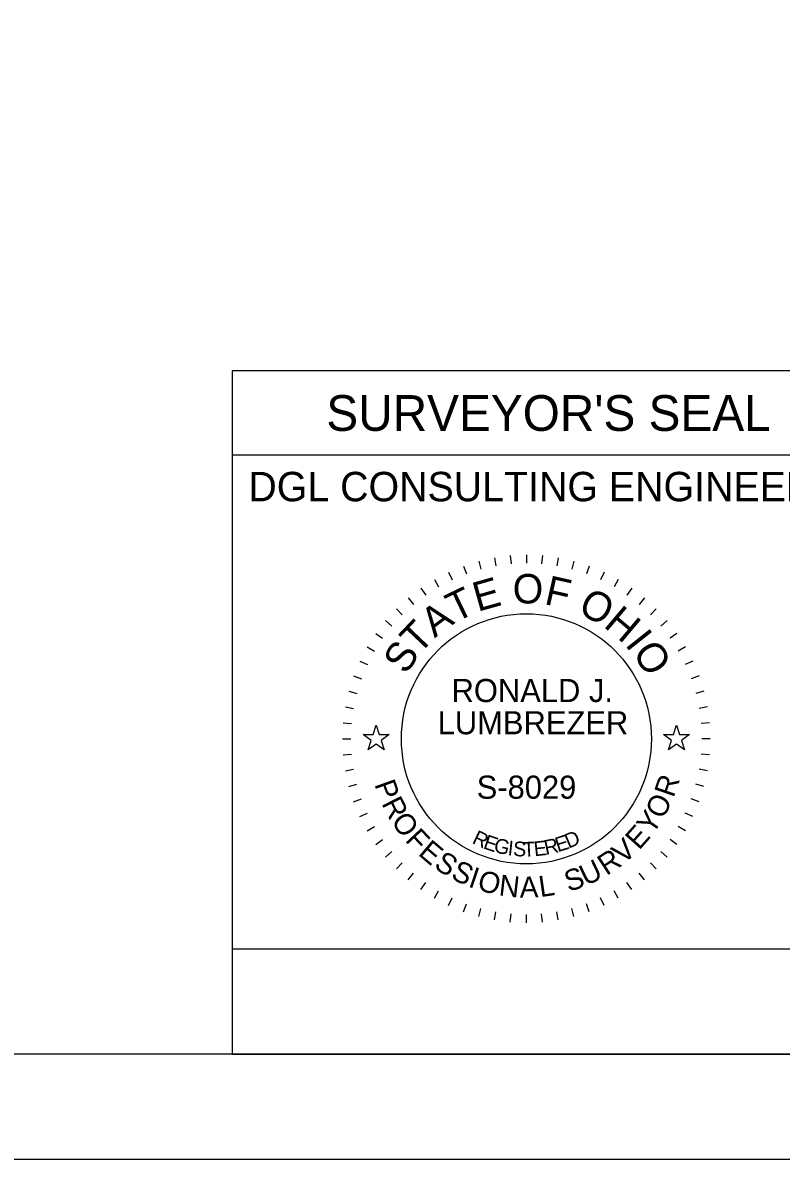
# Model space of a CAD drawing. Extents: x 0 to 34, y 0 to 22.
# Drawn here: x 28.2 to 31.81, y 0 to 5.41 of the extents above; entities that cross this region are included whole.
import ezdxf

# ---------------------------------------------------------------- set-up
doc = ezdxf.new("R2010")
doc.units = 0
for name, color, linetype in [('Default', 7, 'Continuous'), ('SH_Border', 7, 'Continuous'), ('SH_Cut_Line', 7, 'Continuous'), ('SH_Data', 7, 'Continuous')]:
    doc.layers.add(name, color=color, linetype=linetype)

msp = doc.modelspace()

# ---------------------------------------------------------------- linework, layer by layer
at = {"layer": 'Default'}
for points in [[(29.8236, 2.02), (29.8705, 2.02), (29.885, 2.0645), (29.8995, 2.02), (29.9464, 2.02), (29.9085, 1.9924), (29.923, 1.9478), (29.885, 1.9754), (29.847, 1.9478), (29.8615, 1.9924)], [(31.2536, 2.02), (31.3005, 2.02), (31.315, 2.0645), (31.3295, 2.02), (31.3764, 2.02), (31.3385, 1.9924), (31.353, 1.9478), (31.315, 1.9754), (31.277, 1.9478), (31.2915, 1.9924)]]:
    msp.add_lwpolyline(points, close=True, dxfattribs=at)
at = {"layer": 'SH_Border'}
msp.add_lwpolyline([(1.5, 21.5), (33.5, 21.5), (33.5, 0.5), (1.5, 0.5)], close=True, dxfattribs=at)
at = {"layer": 'SH_Cut_Line'}
msp.add_lwpolyline([(0, 0), (34, 0), (34, 22), (0, 22)], close=True, dxfattribs=at)
at = {"layer": 'SH_Data'}
for p, q in [((32, 3.75), (29.2, 3.75)), ((29.2, 3.75), (29.2, 0.5)), ((32, 3.35), (29.2, 3.35)), ((30.5237, 2.8717), (30.5272, 2.8318)), ((30.6, 2.875), (30.6, 2.835)), ((30.6763, 2.8717), (30.6728, 2.8318)), ((30.3007, 2.8222), (30.3144, 2.7846)), ((30.3735, 2.8452), (30.3839, 2.8065)), ((30.4481, 2.8617), (30.455, 2.8223)), ((30.7519, 2.8617), (30.745, 2.8223)), ((30.8265, 2.8452), (30.8161, 2.8065)), ((30.8993, 2.8222), (30.8856, 2.7846)), ((30.1625, 2.7578), (30.1825, 2.7231)), ((30.2302, 2.793), (30.2471, 2.7568)), ((30.9698, 2.793), (30.9529, 2.7568)), ((31.0375, 2.7578), (31.0175, 2.7231)), ((30.0981, 2.7168), (30.1211, 2.684)), ((31.1019, 2.7168), (31.0789, 2.684)), ((30.0376, 2.6703), (30.0633, 2.6396)), ((31.1624, 2.6703), (31.1367, 2.6396)), ((29.9813, 2.6187), (30.0096, 2.5904)), ((31.2187, 2.6187), (31.1904, 2.5904)), ((29.9297, 2.5624), (29.9604, 2.5367)), ((31.2703, 2.5624), (31.2396, 2.5367)), ((29.8832, 2.5019), (29.916, 2.4789)), ((31.3168, 2.5019), (31.284, 2.4789)), ((29.8422, 2.4375), (29.8769, 2.4175)), ((31.3578, 2.4375), (31.3231, 2.4175)), ((29.807, 2.3698), (29.8432, 2.3529)), ((31.393, 2.3698), (31.3568, 2.3529)), ((29.7778, 2.2993), (29.8154, 2.2856)), ((31.4222, 2.2993), (31.3846, 2.2856)), ((29.7548, 2.2265), (29.7935, 2.2161)), ((31.4452, 2.2265), (31.4065, 2.2161)), ((29.7383, 2.1519), (29.7777, 2.145)), ((31.4617, 2.1519), (31.4223, 2.145)), ((29.7283, 2.0763), (29.7682, 2.0728)), ((31.4717, 2.0763), (31.4318, 2.0728)), ((29.725, 2), (29.765, 2)), ((31.475, 2), (31.435, 2)), ((29.7283, 1.9237), (29.7682, 1.9272)), ((31.4717, 1.9237), (31.4318, 1.9272)), ((29.7383, 1.8481), (29.7777, 1.855)), ((31.4617, 1.8481), (31.4223, 1.855)), ((29.7548, 1.7735), (29.7935, 1.7839)), ((31.4452, 1.7735), (31.4065, 1.7839)), ((29.7778, 1.7007), (29.8154, 1.7144)), ((31.4222, 1.7007), (31.3846, 1.7144)), ((29.807, 1.6302), (29.8432, 1.6471)), ((31.393, 1.6302), (31.3568, 1.6471)), ((29.8422, 1.5625), (29.8769, 1.5825)), ((31.3578, 1.5625), (31.3231, 1.5825)), ((29.8832, 1.4981), (29.916, 1.5211)), ((31.3168, 1.4981), (31.284, 1.5211)), ((29.9297, 1.4376), (29.9604, 1.4633)), ((31.2703, 1.4376), (31.2396, 1.4633)), ((29.9813, 1.3813), (30.0096, 1.4096)), ((31.2187, 1.3813), (31.1904, 1.4096)), ((30.0376, 1.3297), (30.0633, 1.3604)), ((31.1624, 1.3297), (31.1367, 1.3604)), ((30.0981, 1.2832), (30.1211, 1.316)), ((31.1019, 1.2832), (31.0789, 1.316)), ((30.1625, 1.2422), (30.1825, 1.2769)), ((31.0375, 1.2422), (31.0175, 1.2769)), ((30.2302, 1.207), (30.2471, 1.2432)), ((30.3007, 1.1778), (30.3144, 1.2154)), ((30.3735, 1.1548), (30.3839, 1.1935)), ((30.8265, 1.1548), (30.8161, 1.1935)), ((30.8993, 1.1778), (30.8856, 1.2154)), ((30.9698, 1.207), (30.9529, 1.2432)), ((30.4481, 1.1383), (30.455, 1.1777)), ((30.5237, 1.1283), (30.5272, 1.1682)), ((30.6, 1.125), (30.6, 1.165)), ((30.6763, 1.1283), (30.6728, 1.1682)), ((30.7519, 1.1383), (30.745, 1.1777)), ((32, 0.5), (29.2, 0.5)), ((32, 0.5), (29.2, 0.5))]:
    msp.add_line(p, q, dxfattribs=at)
msp.add_lwpolyline([(32, 0.5), (32, 1), (29.2, 1), (29.2, 0.5)], close=True, dxfattribs=at)
msp.add_circle((30.6, 2), 0.595, dxfattribs=at)

# ---------------------------------------------------------------- texts
for s, height, p in [("SURVEYOR'S SEAL", 0.17, (29.6478, 3.465)), ('DGL CONSULTING ENGINEERS', 0.14, (29.2766, 3.13)), ('RONALD J.', 0.11, (30.2441, 2.1749)), ('LUMBREZER', 0.11, (30.1779, 2.0216)), ('S-8029', 0.11, (30.3636, 1.7151))]:
    msp.add_text(s, height=height, dxfattribs=at).set_placement(p)
for s, height, rotation, p in [('E', 0.14, 15.7571, (30.3684, 2.6038)), ('O', 0.14, 359.7812, (30.5347, 2.6443)), ('F', 0.14, 347.4362, (30.6811, 2.6417)), ('T', 0.14, 25.7167, (30.2616, 2.5518)), ('O', 0.14, 332.2586, (30.8398, 2.6015)), ('A', 0.14, 36.4747, (30.1634, 2.4781)), ('H', 0.14, 319.9136, (30.9632, 2.5361)), ('T', 0.14, 46.4344, (30.0883, 2.3964)), ('I', 0.14, 308.367, (31.0665, 2.4483)), ('S', 0.14, 57.1924, (30.0281, 2.3014)), ('O', 0.14, 303.1491, (31.1021, 2.4089)), ('P', 0.1, 289.7431, (29.8753, 1.7841)), ('R', 0.1, 70.983, (31.3009, 1.7167)), ('O', 0.1, 62.7428, (31.2501, 1.6133)), ('R', 0.1, 296.9802, (29.9093, 1.6927)), ('O', 0.1, 304.7158, (29.9532, 1.6079)), ('Y', 0.1, 55.5058, (31.2, 1.54)), ('F', 0.1, 312.956, (30.0192, 1.5158)), ('E', 0.1, 48.2687, (31.1366, 1.4673)), ('E', 0.1, 319.6885, (30.0808, 1.4504)), ('R', 0.07, 334.487, (30.3375, 1.5051)), ('E', 0.07, 341.04, (30.3906, 1.4801)), ('G', 0.07, 347.4752, (30.4414, 1.4618)), ('I', 0.07, 353.7858, (30.5091, 1.4468)), ('E', 0.07, 6.0117, (30.6389, 1.4412)), ('R', 0.07, 11.9184, (30.6925, 1.4474)), ('E', 0.07, 17.6836, (30.7498, 1.4602)), ('D', 0.07, 23.3052, (30.801, 1.477)), ('V', 0.1, 41.0316, (31.0615, 1.4007)), ('S', 0.07, 356.8926, (30.5358, 1.4429)), ('T', 0.07, 3.0061, (30.5857, 1.4387)), ('R', 0.1, 33.296, (30.9815, 1.3473)), ('S', 0.1, 326.9255, (30.1554, 1.3885)), ('S', 0.1, 334.1626, (30.236, 1.3374)), ('U', 0.1, 25.5604, (30.8833, 1.2986)), ('I', 0.1, 341.3997, (30.3191, 1.2979)), ('O', 0.1, 345.1351, (30.3618, 1.2821)), ('N', 0.1, 353.3752, (30.466, 1.2555)), ('S', 0.1, 18.3234, (30.8005, 1.2711)), ('A', 0.1, 1.1108, (30.5692, 1.2443)), ('L', 0.1, 8.3479, (30.6664, 1.2467))]:
    msp.add_text(s, height=height, rotation=rotation, dxfattribs=at).set_placement(p)

doc.saveas('drawing.dxf')
